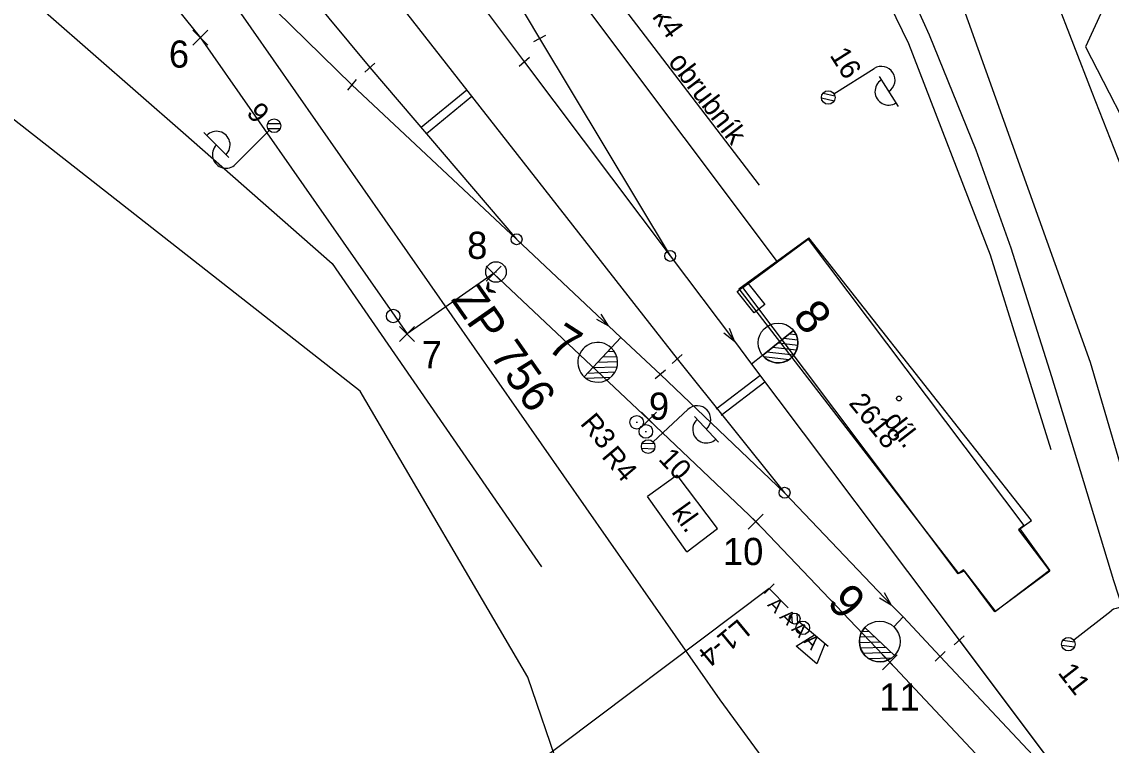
# Model space of a CAD drawing. Extents: x -804166 to -803706, y -1151030 to -1150147.
# Drawn here: x -803990.8 to -803910.7, y -1150447.5 to -1150394.2 of the extents above; entities that cross this region are included whole.
import ezdxf

# ---------------------------------------------------------------- set-up
doc = ezdxf.new("R2010")
doc.units = 0
for name, color, linetype in [('0381KM032-037P - Vrstva 1', 7, 'Continuous'), ('0381KM032-037P - Vrstva 2', 7, 'Continuous'), ('0381KM032-037P - Vrstva 23', 7, 'Continuous'), ('0381KM032-037P - Vrstva 25', 7, 'Continuous'), ('0381KM032-037P - Vrstva 27', 7, 'Continuous'), ('0381KM032-037P - Vrstva 3', 7, 'Continuous'), ('0381KM032-037P - Vrstva 33', 7, 'Continuous'), ('0381KM032-037P - Vrstva 36', 7, 'Continuous'), ('0381KM032-037P - Vrstva 4', 7, 'Continuous'), ('0381KM032-037P - Vrstva 49', 7, 'Continuous'), ('0381KM032-037P - Vrstva 51', 7, 'Continuous'), ('0381KM032-037P - Vrstva 55', 7, 'Continuous'), ('0381KM032-037P - Vrstva 57', 7, 'Continuous'), ('0381KM032-037P - Vrstva 59', 7, 'Continuous'), ('0381KM032-037P - Vrstva 6', 7, 'Continuous'), ('0381KM032-037P - Vrstva 7', 7, 'Continuous'), ('Default', 7, 'Continuous'), ('hran DP - hran DP', 7, 'Continuous'), ('PSR_C2_2_Lomove_body_Vimperk - Vrstva 60', 7, 'Continuous'), ('PSR_C2_2_trasa_Vimperk - Kabelová trasa', 7, 'Continuous'), ('vyt_sit - ohrožené', 7, 'Continuous')]:
    doc.layers.add(name, color=color, linetype=linetype)

msp = doc.modelspace()

# ---------------------------------------------------------------- linework, layer by layer
at = {"layer": '0381KM032-037P - Vrstva 1'}
msp.add_line((-803925.981, -1150438.008), (-803923.249, -1150440.918), dxfattribs=at)
for points in [[(-804090.387, -1150214.375), (-804086.648, -1150219.546), (-804073.823, -1150237.114), (-804072.555, -1150238.826), (-804064.047, -1150250.31), (-804062.807, -1150251.974), (-804052.288, -1150266.049), (-804042.5, -1150279.11), (-804026.546, -1150300.334), (-804011.272, -1150320.629), (-803993.373, -1150344.487), (-803965.171, -1150382.072), (-803953.841, -1150397.189)], [(-804093.97, -1150217.423), (-804088.165, -1150225.674), (-804077.507, -1150240.279), (-804068.519, -1150252.214), (-804067.312, -1150253.815), (-804055.014, -1150270.122), (-804046.09, -1150281.931), (-804030.046, -1150303.209), (-804014.756, -1150323.518), (-803996.92, -1150347.354), (-803968.884, -1150385.416), (-803942.597, -1150419.033)], [(-804095.554, -1150218.377), (-804090.738, -1150227.081), (-804084.011, -1150238.21), (-804078.761, -1150245.777), (-804072.115, -1150254.848), (-804070.853, -1150256.555), (-804059.975, -1150271.287), (-804049.56, -1150285.37), (-804034.127, -1150306.216), (-804018.794, -1150326.862), (-804001.176, -1150350.631), (-803980.37, -1150378.683), (-803972.82, -1150388.417), (-803965.206, -1150397.597)], [(-804011.14, -1150262.39), (-804005.45, -1150273.41), (-803998.73, -1150284.85), (-803991.51, -1150295.63), (-803978.8, -1150312.77), (-803963.69, -1150332.99), (-803952.21, -1150348.36), (-803946.3, -1150356.39), (-803941.6, -1150363.14), (-803936.71, -1150370.83), (-803932.05, -1150378.84), (-803927.78, -1150386.91), (-803924.06, -1150395.18), (-803920.62, -1150403.65), (-803918.06, -1150410.86), (-803915.07, -1150420.32), (-803912.96, -1150427.25), (-803910.49, -1150435.34), (-803907.334, -1150445.05), (-803903.668, -1150454.381), (-803897.938, -1150464.596), (-803891.973, -1150476.598)], [(-803962.118, -1150376.153), (-803948.983, -1150393.601), (-803935.254, -1150411.887)], [(-803963.662, -1150377.119), (-803952.72, -1150395.461)], [(-803974.334, -1150391.21), (-803966.535, -1150398.856)], [(-803975.617, -1150392.296), (-803939.473, -1150444.116), (-803928.265, -1150459.416), (-803914.534, -1150477.731)], [(-803952.72, -1150395.461), (-803943.112, -1150411.456), (-803938.373, -1150417.729), (-803937.129, -1150419.412)], [(-803953.841, -1150397.189), (-803943.112, -1150411.456), (-803938.373, -1150417.729), (-803937.129, -1150419.412)], [(-803965.206, -1150397.597), (-803954.41, -1150410.231), (-803947.654, -1150416.589), (-803946.748, -1150417.444)], [(-803966.535, -1150398.856), (-803954.41, -1150410.231), (-803947.654, -1150416.589), (-803946.748, -1150417.444)], [(-803946.748, -1150417.444), (-803943.834, -1150420.169)], [(-803942.597, -1150419.033), (-803934.696, -1150428.881), (-803926.85, -1150437.116), (-803925.981, -1150438.008)], [(-803937.129, -1150419.412), (-803921.855, -1150439.729)], [(-803943.834, -1150420.169), (-803934.696, -1150428.881), (-803926.85, -1150437.116), (-803925.981, -1150438.008)], [(-803921.855, -1150439.729), (-803911.864, -1150453.035), (-803902.83, -1150465.067), (-803901.897, -1150466.329)], [(-803923.249, -1150440.918), (-803911.864, -1150453.035), (-803902.83, -1150465.067), (-803901.897, -1150466.329)]]:
    msp.add_lwpolyline(points, dxfattribs=at)
at = {"layer": '0381KM032-037P - Vrstva 2'}
for p, q in [((-803952.278, -1150395.227), (-803953.162, -1150395.695)), ((-803952.72, -1150395.461), (-803943.112, -1150411.456)), ((-803964.834, -1150397.263), (-803965.578, -1150397.931)), ((-803953.461, -1150396.864), (-803954.221, -1150397.514)), ((-803965.206, -1150397.597), (-803954.41, -1150410.231)), ((-803966.224, -1150398.465), (-803966.846, -1150399.247)), ((-803936.326, -1150418.769), (-803934.035, -1150416.947)), ((-803934.035, -1150416.947), (-803936.325, -1150418.77)), ((-803934.332, -1150417.184), (-803933.858, -1150417.238)), ((-803949.432, -1150420.36), (-803946.748, -1150417.444)), ((-803935.162, -1150417.844), (-803933.728, -1150418.008)), ((-803934.748, -1150417.514), (-803933.739, -1150417.629)), ((-803949.441, -1150420.356), (-803947.452, -1150418.209)), ((-803947.044, -1150418.871), (-803948.102, -1150418.912)), ((-803947.214, -1150418.497), (-803947.737, -1150418.517)), ((-803942.22, -1150418.704), (-803942.974, -1150419.362)), ((-803936.326, -1150418.77), (-803937.129, -1150419.412)), ((-803936.325, -1150418.77), (-803936.326, -1150418.769)), ((-803936.249, -1150418.852), (-803934.363, -1150419.068)), ((-803935.993, -1150418.504), (-803934.008, -1150418.73)), ((-803935.578, -1150418.174), (-803933.814, -1150418.375)), ((-803947.027, -1150419.63), (-803948.833, -1150419.7)), ((-803946.986, -1150419.248), (-803948.468, -1150419.305)), ((-803942.597, -1150419.033), (-803934.696, -1150428.881)), ((-803949.44, -1150420.356), (-803949.441, -1150420.356)), ((-803947.516, -1150420.41), (-803949.285, -1150420.478)), ((-803947.184, -1150420.017), (-803949.198, -1150420.094)), ((-803943.447, -1150419.852), (-803944.221, -1150420.486)), ((-803925.981, -1150438.008), (-803926.667, -1150438.735)), ((-803926.606, -1150440.856), (-803928.788, -1150438.797)), ((-803928.788, -1150438.797), (-803926.606, -1150440.856)), ((-803929.154, -1150439.486), (-803928.09, -1150439.455)), ((-803928.995, -1150439.081), (-803928.501, -1150439.068)), ((-803921.481, -1150439.397), (-803922.229, -1150440.061)), ((-803921.855, -1150439.729), (-803911.864, -1150453.035)), ((-803929.192, -1150439.888), (-803927.678, -1150439.844)), ((-803929.121, -1150440.286), (-803927.266, -1150440.232)), ((-803922.888, -1150440.573), (-803923.61, -1150441.263)), ((-803928.926, -1150440.681), (-803926.856, -1150440.62)), ((-803928.533, -1150441.069), (-803926.793, -1150441.019))]:
    msp.add_line(p, q, dxfattribs=at)
for points in [[(-803953.841, -1150397.189), (-803943.112, -1150411.456), (-803938.373, -1150417.729), (-803937.129, -1150419.412)], [(-803966.535, -1150398.856), (-803954.41, -1150410.231), (-803947.654, -1150416.589), (-803946.748, -1150417.444)], [(-803948.535, -1150416.116), (-803947.654, -1150416.589), (-803948.18, -1150415.739)], [(-803939.162, -1150417.114), (-803938.373, -1150417.729), (-803938.749, -1150416.802)], [(-803943.834, -1150420.169), (-803934.696, -1150428.881), (-803926.85, -1150437.116), (-803925.981, -1150438.008)], [(-803927.709, -1150436.605), (-803926.85, -1150437.116), (-803927.339, -1150436.244)], [(-803923.249, -1150440.918), (-803911.864, -1150453.035), (-803901.897, -1150466.329)]]:
    msp.add_lwpolyline(points, dxfattribs=at)
for centre, radius in [((-803954.41, -1150410.231), 0.4), ((-803943.112, -1150411.456), 0.4), ((-803935.173, -1150417.854), 1.462), ((-803934.696, -1150428.881), 0.4), ((-803927.697, -1150439.826), 1.5)]:
    msp.add_circle(centre, radius, dxfattribs=at)
for centre, radius, start, end in [((-803935.18, -1150417.858), 1.464, 218.52891, 38.48976), ((-803948.446, -1150419.28), 1.462, 47.14037, 227.60989), ((-803948.445, -1150419.282), 1.464, 227.22989, 47.19074), ((-803927.697, -1150439.826), 1.5, 136.65549, 316.65549)]:
    msp.add_arc(centre, radius, start, end, dxfattribs=at)
at = {"layer": '0381KM032-037P - Vrstva 23'}
for p, q in [((-803938.071, -1150413.885), (-803932.913, -1150410.127)), ((-803916.52, -1150430.915), (-803932.913, -1150410.127)), ((-803938.071, -1150413.885), (-803921.901, -1150434.824)), ((-803942.605, -1150427.597), (-803944.792, -1150429.161)), ((-803939.631, -1150431.514), (-803942.605, -1150427.597)), ((-803941.885, -1150433.226), (-803944.792, -1150429.161)), ((-803917.389, -1150431.545), (-803916.52, -1150430.915)), ((-803941.885, -1150433.226), (-803939.631, -1150431.514)), ((-803939.631, -1150431.514), (-803939.631, -1150431.514)), ((-803917.389, -1150431.545), (-803915.2, -1150434.565)), ((-803921.901, -1150434.824), (-803921.458, -1150434.637)), ((-803919.171, -1150437.591), (-803921.458, -1150434.637)), ((-803919.171, -1150437.591), (-803915.2, -1150434.565)), ((-803919.171, -1150437.591), (-803919.171, -1150437.591))]:
    msp.add_line(p, q, dxfattribs=at)
at = {"layer": '0381KM032-037P - Vrstva 25'}
for p, q in [((-803931.062, -1150399.53), (-803928.104, -1150397.66)), ((-803927.73, -1150398.251), (-803926.341, -1150400.449)), ((-803931.864, -1150399.471), (-803931.006, -1150399.664)), ((-803931.982, -1150399.828), (-803931.048, -1150400.039)), ((-803971.78, -1150401.734), (-803972.737, -1150401.734)), ((-803971.817, -1150402.109), (-803972.696, -1150402.109)), ((-803975.581, -1150404.208), (-803977.42, -1150402.37)), ((-803972.612, -1150402.228), (-803975.086, -1150404.703)), ((-803944.371, -1150425.139), (-803941.814, -1150422.749)), ((-803941.336, -1150423.26), (-803939.56, -1150425.159)), ((-803945.169, -1150425.232), (-803944.29, -1150425.261)), ((-803945.218, -1150425.605), (-803944.262, -1150425.637)), ((-803913.427, -1150439.714), (-803910.666, -1150437.563)), ((-803914.23, -1150439.734), (-803913.357, -1150439.842)), ((-803914.313, -1150440.101), (-803913.362, -1150440.219))]:
    msp.add_line(p, q, dxfattribs=at)
msp.add_lwpolyline([(-803938.176, -1150414.066), (-803937.39, -1150413.447), (-803936.152, -1150415.018), (-803936.938, -1150415.637), (-803938.176, -1150414.066)], dxfattribs=at)
for centre in [(-803931.485, -1150399.797), (-803931.485, -1150399.797), (-803972.258, -1150401.874), (-803972.258, -1150401.874), (-803944.736, -1150425.481), (-803913.821, -1150440.021)]:
    msp.add_circle(centre, 0.5, dxfattribs=at)
for centre, start, end in [((-803927.57, -1150398.505), 302.29869, 122.29869), ((-803927.046, -1150399.357), 121.59611, 303.00126), ((-803976.492, -1150403.28), 314.30437, 135.70951), ((-803975.793, -1150403.996), 135.00694, 315.00694), ((-803941.131, -1150423.479), 313.08042, 133.08042), ((-803940.457, -1150424.218), 132.37785, 313.78299), ((-803910.051, -1150438.352), 307.9199, 127.9199)]:
    msp.add_arc(centre, 1, start, end, dxfattribs=at)
at = {"layer": '0381KM032-037P - Vrstva 27'}
for p, q in [((-803945.625, -1150423.694), (-803945.525, -1150423.694)), ((-803944.953, -1150424.366), (-803944.853, -1150424.366)), ((-803933.408, -1150438.822), (-803933.308, -1150438.822))]:
    msp.add_line(p, q, dxfattribs=at)
for centre in [(-803945.575, -1150423.694), (-803944.903, -1150424.366), (-803933.358, -1150438.822)]:
    msp.add_circle(centre, 0.5, dxfattribs=at)
at = {"layer": '0381KM032-037P - Vrstva 33'}
for p, q in [((-803934.191, -1150437.821), (-803934.134, -1150438.5)), ((-803933.793, -1150437.779), (-803933.735, -1150438.472)), ((-803931.499, -1150440.186), (-803933.637, -1150438.384)), ((-803933.842, -1150440.17), (-803932.492, -1150439.347)), ((-803932.314, -1150441.461), (-803933.842, -1150440.17)), ((-803931.728, -1150439.992), (-803932.314, -1150441.461))]:
    msp.add_line(p, q, dxfattribs=at)
msp.add_circle((-803933.957, -1150438.143), 0.401, dxfattribs=at)
msp.add_circle((-803933.957, -1150438.143), 0.401, dxfattribs=at)
at = {"layer": '0381KM032-037P - Vrstva 36'}
msp.add_circle((-803963.496, -1150415.874), 0.5, dxfattribs=at)
at = {"layer": '0381KM032-037P - Vrstva 4'}
msp.add_lwpolyline([(-804015.087, -1150257.699), (-804005.607, -1150276.645), (-803997.811, -1150289.613), (-803985.988, -1150305.967), (-803963.827, -1150335.545), (-803947.69, -1150357.387), (-803941.599, -1150366.016), (-803933.495, -1150379.543), (-803925.569, -1150395.827), (-803919.567, -1150411.363), (-803915.11, -1150425.701)], dxfattribs=at)
at = {"layer": '0381KM032-037P - Vrstva 49'}
for points in [[(-804010.873, -1150255.863), (-804001.608, -1150274.672), (-803994.699, -1150286.679), (-803981.461, -1150304.357), (-803936.046, -1150366.093), (-803921.768, -1150392.538), (-803912.222, -1150419.282), (-803908.812, -1150430.908)], [(-803920.94, -1150376.21), (-803910.018, -1150390.511), (-803912.553, -1150396.059), (-803903.866, -1150412.95), (-803903.684, -1150418.644), (-803901.421, -1150428.97), (-803900.537, -1150437.639), (-803895.89, -1150448.56), (-803892.01, -1150457.3), (-803887.412, -1150463.602), (-803875.883, -1150484.91), (-803874.859, -1150484.495), (-803872.322, -1150492.497), (-803872.997, -1150496.546), (-803874.041, -1150498.946)], [(-803995.514, -1150387.867), (-803978.951, -1150402.371), (-803967.974, -1150412.011), (-803952.572, -1150434.32)]]:
    msp.add_lwpolyline(points, dxfattribs=at)
at = {"layer": '0381KM032-037P - Vrstva 51'}
msp.add_line((-803947.116, -1150392.441), (-803936.561, -1150406.256), dxfattribs=at)
msp.add_lwpolyline([(-804015.087, -1150257.699), (-804005.607, -1150276.645), (-803997.811, -1150289.613), (-803985.988, -1150305.967), (-803963.827, -1150335.545), (-803947.69, -1150357.387), (-803941.599, -1150366.016), (-803933.495, -1150379.543), (-803925.569, -1150395.827), (-803919.567, -1150411.363), (-803915.11, -1150425.701)], dxfattribs=at)
at = {"layer": '0381KM032-037P - Vrstva 55'}
msp.add_lwpolyline([(-803937.77, -1150413.78), (-803932.96, -1150410.23), (-803917.09, -1150431.3), (-803917.49, -1150431.6), (-803915.17, -1150434.66), (-803919.22, -1150437.65), (-803921.53, -1150434.55), (-803921.93, -1150434.85)], close=True, dxfattribs=at)
at = {"layer": '0381KM032-037P - Vrstva 59'}
msp.add_circle((-803926.281, -1150421.943), 0.175, dxfattribs=at)
at = {"layer": '0381KM032-037P - Vrstva 6'}
for p, q in [((-803935.462, -1150435.582), (-803936.176, -1150436.284)), ((-803935.819, -1150435.933), (-803966.226, -1150458.779)), ((-803934.431, -1150437.345), (-803935.819, -1150435.933))]:
    msp.add_line(p, q, dxfattribs=at)
at = {"layer": '0381KM032-037P - Vrstva 7'}
for p, q in [((-803958.064, -1150399.253), (-803961.44, -1150402.011)), ((-803957.695, -1150399.725), (-803961.051, -1150402.467)), ((-803939.724, -1150422.708), (-803936.506, -1150420.241)), ((-803939.354, -1150423.181), (-803936.145, -1150420.721))]:
    msp.add_line(p, q, dxfattribs=at)
at = {"layer": 'hran DP - hran DP'}
for p, q in [((-803965.92, -1150421.41), (-804004.05, -1150391.51)), ((-803914.94, -1150392.05), (-803912.08, -1150399.4)), ((-803912.08, -1150399.4), (-803907, -1150412.45)), ((-803953.58, -1150442.45), (-803965.92, -1150421.41)), ((-803944.36, -1150469.51), (-803953.58, -1150442.45))]:
    msp.add_line(p, q, dxfattribs=at)
at = {"layer": 'PSR_C2_2_Lomove_body_Vimperk - Vrstva 60'}
for p, q in [((-803978.229, -1150395.947), (-803977.129, -1150394.847)), ((-803977.129, -1150395.947), (-803978.229, -1150394.847)), ((-803956.656, -1150413.305), (-803955.556, -1150412.205)), ((-803955.556, -1150413.305), (-803956.656, -1150412.205)), ((-803963.026, -1150417.743), (-803961.926, -1150416.643)), ((-803961.926, -1150417.743), (-803963.026, -1150416.643)), ((-803945.23, -1150424.057), (-803944.13, -1150422.957)), ((-803944.13, -1150424.057), (-803945.23, -1150422.957)), ((-803937.368, -1150431.553), (-803936.268, -1150430.453)), ((-803936.268, -1150431.553), (-803937.368, -1150430.453)), ((-803927.505, -1150441.905), (-803926.405, -1150440.805)), ((-803926.405, -1150441.905), (-803927.505, -1150440.805))]:
    msp.add_line(p, q, dxfattribs=at)
at = {"layer": 'PSR_C2_2_trasa_Vimperk - Kabelová trasa'}
for p, q in [((-803977.679, -1150395.397), (-803962.476, -1150417.193)), ((-803956.106, -1150412.755), (-803962.476, -1150417.193)), ((-803956.106, -1150412.755), (-803944.68, -1150423.507)), ((-803944.68, -1150423.507), (-803936.818, -1150431.003)), ((-803936.818, -1150431.003), (-803926.955, -1150441.355)), ((-803926.955, -1150441.355), (-803914.05, -1150455.089))]:
    msp.add_line(p, q, dxfattribs=at)
msp.add_lwpolyline([(-804006.069, -1150356.3), (-803990.083, -1150380.012), (-803977.679, -1150395.397)], dxfattribs=at)
at = {"layer": 'vyt_sit - ohrožené'}
msp.add_line((-803955.981, -1150412.633), (-803955.881, -1150412.633), dxfattribs=at)
msp.add_circle((-803955.931, -1150412.633), 0.756, dxfattribs=at)

# ---------------------------------------------------------------- texts
at = {"layer": '0381KM032-037P - Vrstva 2'}
for s, rotation, p in [('8', 308.50934, (-803934.183, -1150415.962)), ('7', 327.21032, (-803952.278, -1150418.346)), ('9', 311.65549, (-803931.656, -1150436.995))]:
    msp.add_text(s, height=2.5, rotation=rotation, dxfattribs=at).set_placement(p)
at = {"layer": '0381KM032-037P - Vrstva 23'}
for s, rotation, p in [('díl.', 307.67687, (-803927.463, -1150423.603)), ('kl.', 305.56966, (-803943.057, -1150430.309))]:
    msp.add_text(s, height=1.5, rotation=rotation, dxfattribs=at).set_placement(p)
at = {"layer": '0381KM032-037P - Vrstva 25'}
for s, rotation, p in [('16', 302.29869, (-803931.415, -1150396.684)), ('9', 310.00694, (-803974.353, -1150400.957)), ('10', 313.08042, (-803944.04, -1150426.443)), ('11', 307.9199, (-803914.644, -1150442.133))]:
    msp.add_text(s, height=1.5, rotation=rotation, dxfattribs=at).set_placement(p)
at = {"layer": '0381KM032-037P - Vrstva 27'}
for s, p in [('R3', (-803949.788, -1150423.809)), ('R4', (-803948.214, -1150426.236))]:
    msp.add_text(s, height=1.5, rotation=310, dxfattribs=at).set_placement(p)
at = {"layer": '0381KM032-037P - Vrstva 3'}
msp.add_text('Vk4', height=1.5, rotation=305.71645, dxfattribs=at).set_placement((-803945.266, -1150392.776))
at = {"layer": '0381KM032-037P - Vrstva 51'}
msp.add_text('obrubník', height=1.5, rotation=307.38072, dxfattribs=at).set_placement((-803943.316, -1150397.186))
at = {"layer": '0381KM032-037P - Vrstva 57'}
msp.add_text('2618', height=1.5, rotation=309.10252, dxfattribs=at).set_placement((-803930.031, -1150422.302))
at = {"layer": '0381KM032-037P - Vrstva 6'}
for s, height, rotation, p in [('  A A A A ', 1, 314.51818, (-803936.532, -1150436.634)), ('L1-4', 1.5, 219.51818, (-803938.057, -1150438.079))]:
    msp.add_text(s, height=height, rotation=rotation, dxfattribs=at).set_placement(p)
at = {"layer": 'Default'}
for s, p in [('6', (-803979.999, -1150397.599)), ('8', (-803958.05, -1150411.671)), ('7', (-803961.393, -1150419.721)), ('9', (-803944.68, -1150423.507)), ('10', (-803939.232, -1150434.201)), ('11', (-803927.728, -1150444.908))]:
    msp.add_text(s, height=2, dxfattribs=at).set_placement(p)
at = {"layer": 'vyt_sit - ohrožené'}
msp.add_text('ŽP 756', height=2.4, rotation=305, dxfattribs=at).set_placement((-803959.295, -1150414.657))

doc.saveas('drawing.dxf')
